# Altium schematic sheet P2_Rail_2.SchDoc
size 368 x 228 mm
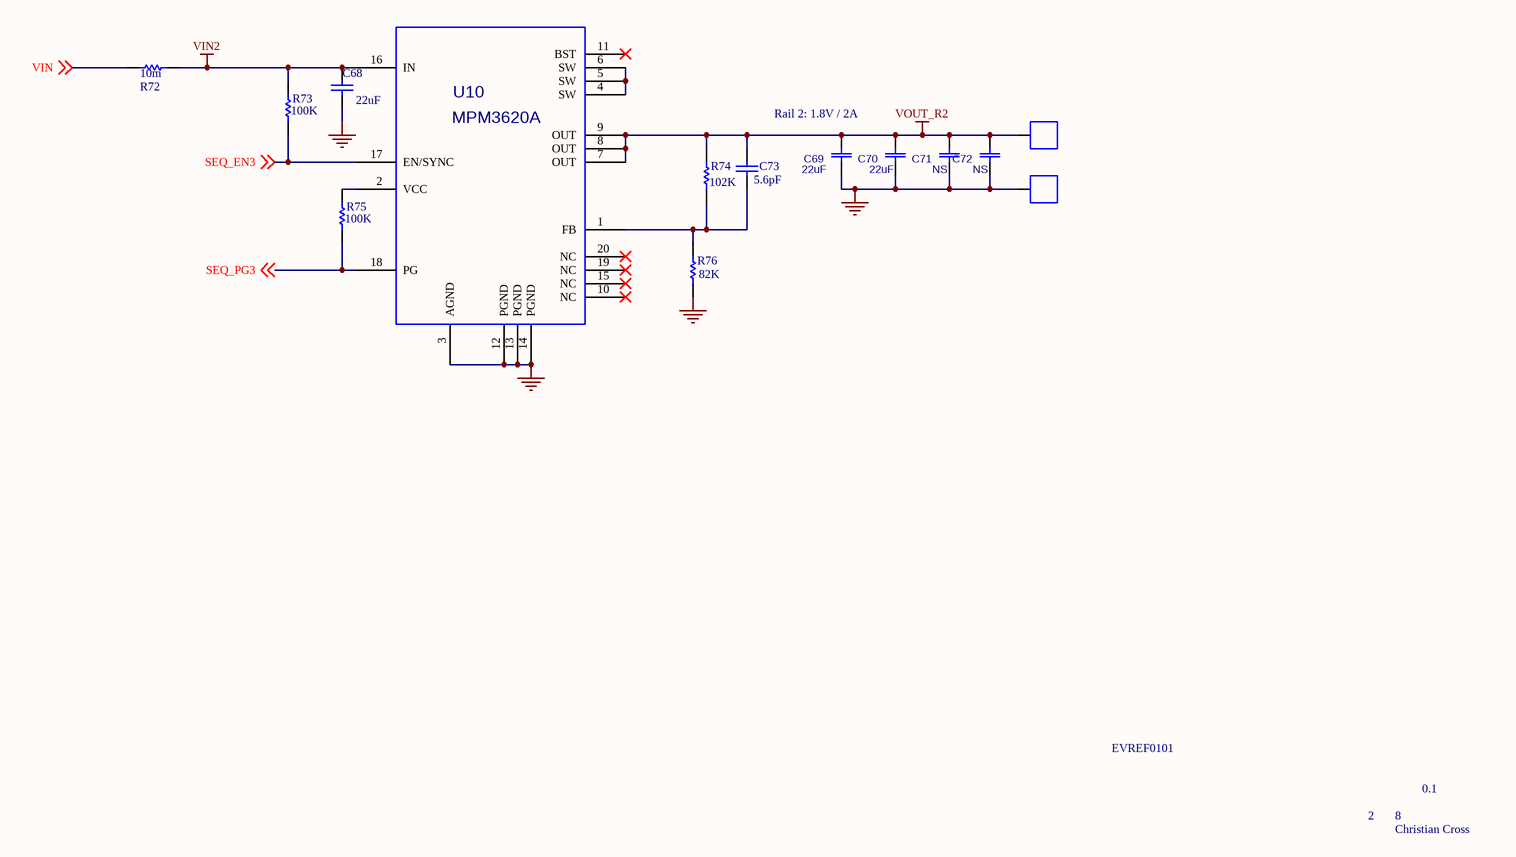
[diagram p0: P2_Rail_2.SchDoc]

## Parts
C68  22uF  [CAP0805]
C69  22uF  [CAP0805]
C70  22uF  [CAP0805]
C71  NS  [CAP0805]
C72  NS  [CAP0805]
C73  5.6pF  [CAP0603]
CN17  *  [TP2MM]  (value not drawn)
CN18  *  [TP2MM]  (value not drawn)
R72  10m  [RES/0805]
R73  100K  [RES0603]
R74  102K  [RES0603]
R75  100K  [RES0603]
R76  82K  [RES0603]
U10  MPM3620A  [QFN20-3X5MM]

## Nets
GND: C68.1 C69.1 C70.1 C71.1 C72.1 CN18.1 R76.1 U10.3(AGND) U10.12(PGND) U10.13(PGND) U10.14(PGND)
VIN2: C68.2 R72.2 R73.2 U10.16(IN)
VOUT_R2: C69.2 C70.2 C71.2 C72.2 C73.2 CN17.1 R74.2 U10.7(OUT) U10.8(OUT) U10.9(OUT)
SEQ_EN3: R73.1 U10.17(EN/SYNC) ; off-sheet SEQ_EN3
SEQ_PG3: R75.1 U10.18(PG) ; off-sheet SEQ_PG3
VIN: R72.1 ; off-sheet VIN
NetC73_1: C73.1 R74.1 R76.2 U10.1(FB)
NetR75_2: R75.2 U10.2(VCC)
NetU10_4: U10.4(SW) U10.5(SW) U10.6(SW)

Not connected (* = marked no-connect by the designer): U10 10(NC)* 11(BST)* 15(NC)* 19(NC)* 20(NC)*

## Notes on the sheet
- Rail 2: 1.8V / 2A
- EVREF0101
- 2
- 8
- 0.1
- Christian Cross

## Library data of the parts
C68 C73 = Cap: Capacitor
C69-C72 = CAP0805: {Description}; Manufacturer: {Manufacturer}; Manufacturer P/N: {Manufacturer P/N}
CN17 CN18 = TP2MM: {Description}; Manufacturer: {Manufacturer}; Manufacturer P/N: {Manufacturer P/N}
R72 = Res1: Resistor; Value: 10mohm
R73-R76 = Res1: Resistor
U10 = MPM3630A: 18V/3A DC/DC Module Synchronous Step-Down Regulator; Manufacturer: {Manufacturer}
